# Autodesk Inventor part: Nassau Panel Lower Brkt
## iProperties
Shininess: 70.0
Angle Display Precision: 2
Document Length Units: 11269
Document Angle Units: 11279
Document Time Units: 11290
Document Mass Units: 11283
Document Length Units Precision: 3
Document Angle Units Precision: 2
Compacted: True
Created: 2001-08
Part Number: Nassau Panel Lower Brkt
Document SubType Name: Sheet Metal
Designer: Martin Budgell
Density: 0.0
Volumn: 0.0
Area: 0.0
PropertySet Name: Model Information
Control State: 0
Master: False
Checked Out: False
Author: Martin Budgell
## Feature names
1. Extrusion1
2. Hole1
3. Chamfer1
4. Bend3
5. Bend4
